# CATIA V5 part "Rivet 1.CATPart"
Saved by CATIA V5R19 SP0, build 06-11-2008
Part number: Rivet
Bounding box of the stored display mesh (mm): x -8.948 to 8.948, y -4.675 to 39.675, z -8.948 to 8.948
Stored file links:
  G:\EU_thinkMotion\CFAO_2010\St2M_groupe2\St2M_groupe2\csayed\csayed\csayed\Rivet 1.CATPart
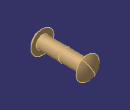
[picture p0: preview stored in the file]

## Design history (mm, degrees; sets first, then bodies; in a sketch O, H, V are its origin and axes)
Body1 (main body)
  Sketch1 "Esquisse.1" on yz-plane, origin (0, 0, 0), H (0, 1, 0), V (0, 0, 1)
    line L1 (0, 5) -> (0, 9)
    point P1 (0, 9)
    arc A1 centre (6.3246, 0) radius 11 from (0, 9) to (-4.6754, 0) ccw
    point P2 (6.3246, 0)
    line L2 (0, 5) -> (17.5, 5)
    point P3 (0, 5)
    point P4 (17.5, 5)
    construction line L3 (17.5, 13.7904) -> (17.5, -16.818)
    point P7 (35, 9)
    line L4 (35, 5) -> (35, 9)
    arc A2 centre (28.6754, 0) radius 11 from (35, 9) to (39.6754, 0) cw
    point P9 (17.5, 5)
    point P10 (35, 5)
    line L5 (35, 5) -> (17.5, 5)
    line L6 (-4.6754, 0) -> (39.6754, 0)
    point P11 (-4.6754, 0)
    distance P2 A1 = 11
    distance L2 H = 5
    vertical: L1 V, L3 V
    horizontal: L2 H, L6 H
    symmetry: P1 P7 L3, L1 L4 L3, A1 A2 L3, P4 P9 L3, P3 P10 L3, L2 L5 L3
    coincidence: P11 H, P4 P9
  Shaft1: profile Sketch1, axis Sketch1.L6, angle 360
